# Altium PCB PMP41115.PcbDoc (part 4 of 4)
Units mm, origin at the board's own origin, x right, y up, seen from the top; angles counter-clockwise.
Board outline 97.92 x 43.13 mm, 4 copper layers (Top Layer, Signal Layer 1, Signal Layer 2, Bottom Layer), stack 1.016 mm thick; 168 components, 122 nets, 522 pads, 2459 vias.
Unrouted connection lines stored in the file: 1.
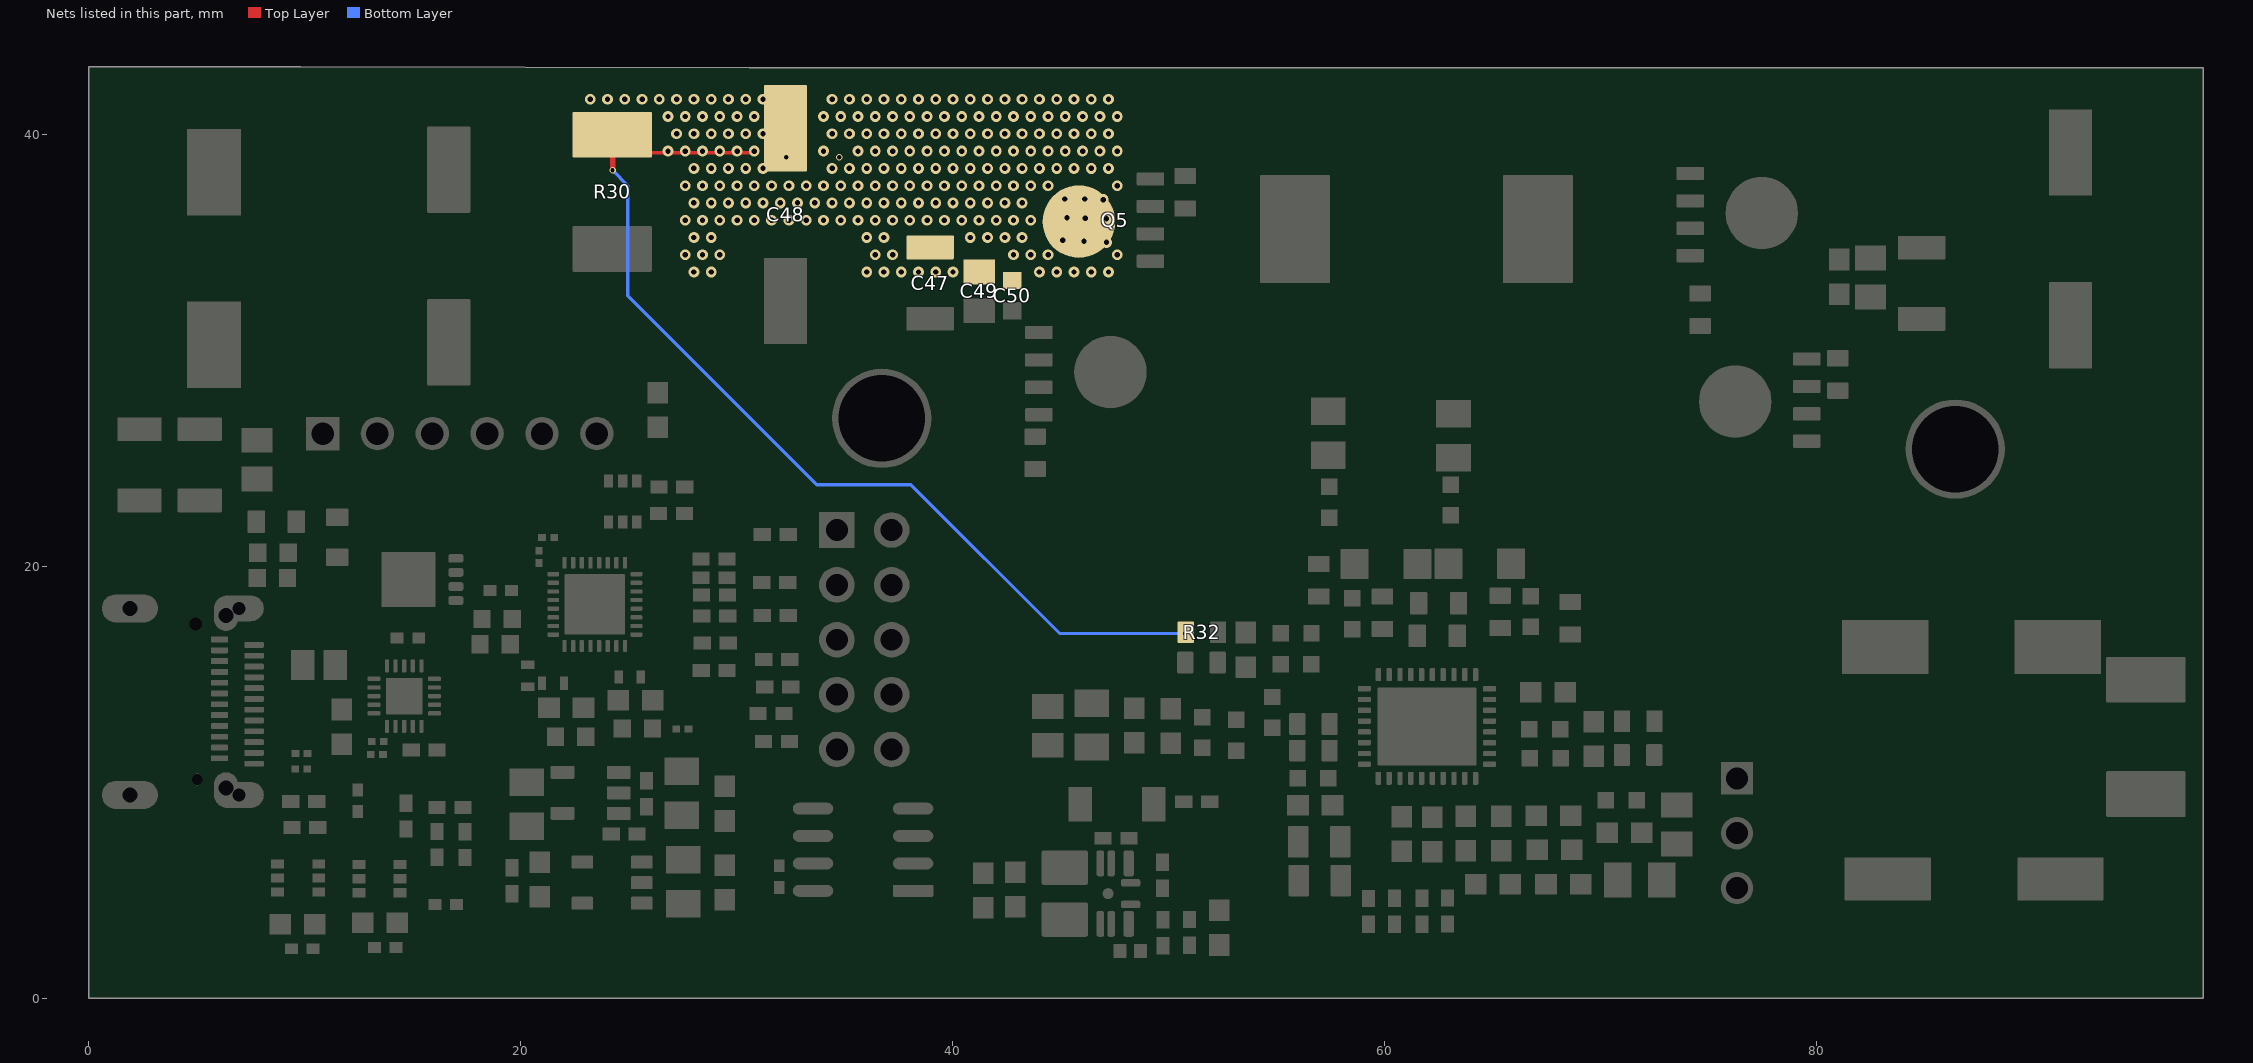
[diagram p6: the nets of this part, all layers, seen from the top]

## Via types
v1: diameter 0.5, hole 0.25, Top Layer to Bottom Layer, 2147 vias
v2: diameter 0.3, hole 0.2, Top Layer to Bottom Layer, tented both sides, 193 vias
v3: diameter 0.5, hole 0.25, Top Layer to Bottom Layer, tented both sides, 61 vias
v4: diameter 0.5, hole 0.2, Top Layer to Bottom Layer, 22 vias
v5: diameter 0.5, hole 0.2, Top Layer to Bottom Layer, tented both sides, 19 vias
v6: diameter 0.61, hole 0.203, Top Layer to Bottom Layer, tented both sides, 13 vias
v7: diameter 0.35, hole 0.2, Top Layer to Bottom Layer, tented both sides, 2 vias
v8: diameter 0.4, hole 0.2, Top Layer to Bottom Layer, tented both sides, 2 vias

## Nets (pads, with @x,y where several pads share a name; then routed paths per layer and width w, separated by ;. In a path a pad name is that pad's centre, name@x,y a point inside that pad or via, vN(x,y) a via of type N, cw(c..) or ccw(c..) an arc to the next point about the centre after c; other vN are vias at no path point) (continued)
VSYS: C47.2 C48.2 C49.1 C50.1 Q5.5-6-7-8 R30.2 R32.2 | length 47
  Top Layer w0.152: R30.2@24.243,39.979 R30.2@24.332,39.89 ; R30.2@24.257,39.091 24.257,39.815 R30.2@24.332,39.89 ; v1@30.863,39.181 30.823,39.141 25.081,39.141 R30.2@24.332,39.89
  Top Layer w0.254: v2(24.257,38.329) 24.257,39.051 24.297,39.091 R30.2@24.308,39.091
  Bottom Layer w0.152: 28.55,28.931 33.706,23.774 38.075,23.774 44.966,16.883 v2(50.764,16.883)
  Bottom Layer w0.154: v2(24.257,38.329) 24.968,37.617 24.968,32.512 28.55,28.931
  other v1: 28.023,33.621 28.823,33.621 36.023,33.621 36.823,33.621 37.623,33.621 38.423,33.621 39.223,33.621 40.023,33.621 44.023,33.621 44.823,33.621 45.623,33.621 46.423,33.621 47.223,33.621 27.623,34.421 28.423,34.421 29.223,34.421 36.423,34.421 37.223,34.421 42.823,34.421 43.623,34.421 44.423,34.421 47.623,34.421 28.023,35.221 28.823,35.221 36.023,35.221 36.823,35.221 40.823,35.221 41.623,35.221 42.423,35.221 43.223,35.221 27.623,36.021 28.423,36.021 29.223,36.021 30.023,36.021 30.823,36.021 31.623,36.021 32.423,36.021 33.223,36.021 34.023,36.021 34.823,36.021 35.623,36.021 36.423,36.021 37.223,36.021 38.023,36.021 38.823,36.021 39.623,36.021 40.423,36.021 41.223,36.021 42.023,36.021 42.823,36.021 43.623,36.021 28.023,36.821 28.823,36.821 29.623,36.821 30.423,36.821 31.223,36.821 32.023,36.821 32.823,36.821 33.623,36.821 34.423,36.821 35.223,36.821 36.023,36.821 36.823,36.821 37.623,36.821 38.423,36.821 39.223,36.821 40.023,36.821 40.823,36.821 41.623,36.821 42.423,36.821 43.223,36.821 27.623,37.621 28.423,37.621 29.223,37.621 30.023,37.621 30.823,37.621 31.623,37.621 32.423,37.621 33.223,37.621 34.023,37.621 34.823,37.621 35.623,37.621 36.423,37.621 37.223,37.621 38.023,37.621 38.823,37.621 39.623,37.621 40.423,37.621 41.223,37.621 42.023,37.621 42.823,37.621 43.623,37.621 44.423,37.621 47.623,37.621 28.023,38.421 28.823,38.421 29.623,38.421 30.423,38.421 31.223,38.421 34.423,38.421 35.223,38.421 36.023,38.421 36.823,38.421 37.623,38.421 38.423,38.421 39.223,38.421 40.023,38.421 40.823,38.421 41.623,38.421 42.423,38.421 43.223,38.421 44.023,38.421 44.823,38.421 45.623,38.421 46.423,38.421 47.223,38.421 26.823,39.221 27.623,39.221 28.423,39.221 29.223,39.221 30.023,39.221 30.823,39.221 34.023,39.221 35.623,39.221 36.423,39.221 37.223,39.221 38.023,39.221 38.823,39.221 39.623,39.221 40.423,39.221 41.223,39.221 42.023,39.221 42.823,39.221 43.623,39.221 44.423,39.221 45.223,39.221 46.023,39.221 46.823,39.221 47.623,39.221 27.223,40.021 28.023,40.021 28.823,40.021 29.623,40.021 30.423,40.021 31.223,40.021 34.423,40.021 35.223,40.021 36.023,40.021 36.823,40.021 37.623,40.021 38.423,40.021 39.223,40.021 40.023,40.021 40.823,40.021 41.623,40.021 42.423,40.021 43.223,40.021 44.023,40.021 44.823,40.021 45.623,40.021 46.423,40.021 47.223,40.021 26.823,40.821 27.623,40.821 28.423,40.821 29.223,40.821 30.023,40.821 30.823,40.821 34.023,40.821 34.823,40.821 35.623,40.821 36.423,40.821 37.223,40.821 38.023,40.821 38.823,40.821 39.623,40.821 40.423,40.821 41.223,40.821 42.023,40.821 42.823,40.821 43.623,40.821 44.423,40.821 45.223,40.821 46.023,40.821 46.823,40.821 47.623,40.821 23.223,41.621 24.023,41.621 24.823,41.621 25.623,41.621 26.423,41.621 27.223,41.621 28.023,41.621 28.823,41.621 29.623,41.621 30.423,41.621 31.223,41.621 34.423,41.621 35.223,41.621 36.023,41.621 36.823,41.621 37.623,41.621 38.423,41.621 39.223,41.621 40.023,41.621 40.823,41.621 41.623,41.621 42.423,41.621 43.223,41.621 44.023,41.621 44.823,41.621 45.623,41.621 46.423,41.621 47.223,41.621
  other v2: 34.747,38.938
  other v3: 47.13,34.995 46.088,35.046 45.098,35.096 47.13,36.087 46.139,36.112 45.301,36.138 46.977,36.976 45.199,37.001 46.114,37.001
  other v6: 32.309,38.938
pads on no net: J1.A2 J1.A3 J1.A10 J1.A11 J1.ALIGN1 J1.ALIGN2 J1.B2 J1.B3 J1.B10 J1.B11 J3.4 Q1.9A Q1.9B Q1.9C Q1.9D U1.21 U2.9 U4.4 U5.1 U5.7 U6.4 U7.15 U7.16 U7.31

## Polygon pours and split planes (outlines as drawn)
VSYS on Top Layer "TOP_LAYER_VSYS_P022" (solid, remove dead copper, pour order 22): 22.198,42.596 22.201,38.684 27.092,38.684 27.044,32.722 29.769,32.722 29.769,35.238 35.364,35.238 35.35,32.723 47.955,32.766 47.955,42.596
NetU5_5 on Top Layer "TOP_LAYER_NETU5_5_P001" (solid, pour order 1): 46.025,2.896 46.05,2.87 47.015,2.87 47.015,3.962 46.965,4.013 46.025,4.013
NetC21_1 on Top Layer "TOP_LAYER_NETC21_1_P115" (solid, remove dead copper, pour order 115): 46.482,7.696 46.482,5.791 46.66,5.613 47.422,5.613 47.523,5.715 47.523,6.807 47.371,6.96 47.371,7.696 46.507,7.696
PPHV on Top Layer "TOP_LAYER_PPHV_P033" (solid, remove dead copper, pour order 33): 0.483,33.223 0.483,24.841 12.065,24.841 12.065,27.127 3.937,27.127 3.937,33.223
VBUS on Top Layer "TOP_LAYER_VBUS_P034" (solid, remove dead copper, pour order 34): 22.174,25.73 18.771,22.327 13.335,22.327 13.335,21.234 10.82,21.234 10.82,16.205 10.82,14.63 13.894,14.63 13.894,17.729 16.408,17.729 16.408,20.142 16.408,20.752 27.457,20.752 27.457,27.127 22.174,27.127
PP5V on Top Layer "TOP_LAYER_PP5V_P114" (solid, remove dead copper, pour order 114): 20.396,18.136 20.828,18.567 21.768,18.567 21.844,18.491 21.844,17.983 21.768,17.907 20.904,17.907 20.371,17.374 20.371,15.85 19.101,15.85 19.101,17.983 19.253,18.136
GND on Top Layer "TOP_LAYER_GND_P095" (solid, remove dead copper, pour order 95): 10.922,11.633 8.23,11.633 8.23,0.61 17.958,0.61 17.958,15.646 10.947,15.646 10.922,15.621
GND on Top Layer "TOP_LAYER_GND_P075" (solid, remove dead copper, pour order 75): 39.821,0.61 79.099,0.61 79.099,6.564 77.552,6.598 77.521,18.948 39.821,18.948
VBUS_LV on Top Layer "TOP_LAYER_VBUS_LV_P054" (solid, remove dead copper, pour order 54): 16.586,17.653 13.919,17.653 13.919,15.646 14.808,15.646 14.808,17.043 17.625,17.043 17.805,17.223 17.805,19.228 18.999,19.228 18.999,18.491 21.692,18.491 21.895,18.694 21.895,19.228 21.742,19.38 21.133,19.38 20.396,20.117 16.586,20.117
GND on Top Layer "TOP_LAYER_GND_P044" (solid, remove dead copper, pour order 44): 17.882,0 41.681,0 41.681,5.436 39.319,5.436 39.319,18.796 17.882,18.796
GND on Top Layer "TOP_LAYER_GND_P036" (solid, remove dead copper, pour order 36): 0.61,4.623 0.61,0.61 8.331,0.61 8.331,24.308 0.61,24.308
GND on Top Layer "TOP_LAYER_GND_P039" (solid, remove dead copper, pour order 39): 12.497,27.813 12.497,24.536 0.686,24.536 0.686,21.641 13.03,21.641 13.03,22.657 19.101,22.657 21.92,25.476 21.92,27.813
VBUS_C on Top Layer "TOP_LAYER_VBUS_C_P038" (solid, remove dead copper, pour order 38): 8.534,22.606 8.534,15.69 6.579,15.705 6.577,13.588 6.579,11.76 10.617,11.76 10.617,22.606
GND on Top Layer "TOP_LAYER_GND_P032" (solid, remove dead copper, pour order 32): 4.115,27.381 28.118,27.408 28.118,21.107 30.378,21.107 30.378,32.41 4.115,32.41
PPHV on Top Layer "TOP_LAYER_PPHV_P031" (solid, remove dead copper, pour order 31): 0.559,42.647 21.514,42.647 21.514,35.763 26.467,35.763 26.467,32.766 20.498,32.766 0.559,32.766
BAT on Top Layer "TOP_LAYER_BAT_P030" (solid, remove dead copper, pour order 30): 88.392,10.338 88.392,0.61 97.434,0.61 97.434,10.338
P_OUT on Top Layer "TOP_LAYER_P_OUT_P029" (solid, remove dead copper, pour order 29): 93.143,33.604 93.089,18.596 88.179,18.596 88.179,13.882 97.739,13.882 97.739,33.604
GND on Top Layer "TOP_LAYER_GND_P028" (solid, remove dead copper, pour order 28): 78.003,0.61 87.478,0.61 87.478,22.149 78.003,22.149
P_OUT on Top Layer "TOP_LAYER_P_OUT_P027" (solid, remove dead copper, pour order 27): 75.311,42.647 75.311,33.426 97.917,33.426 97.917,42.647
GND on Top Layer "TOP_LAYER_GND_P026" (solid, remove dead copper, pour order 26): 78.537,19.177 85.7,19.177 93.269,19.177 93.269,33.249 78.537,33.249
SW2 on Top Layer "TOP_LAYER_SW2_P025" (solid, remove dead copper, pour order 25): 60.858,23.52 78.207,23.52 78.207,32.461 74.969,32.461 75.006,42.672 60.858,42.672
SW1 on Top Layer "TOP_LAYER_SW1_P024" (solid, remove dead copper, pour order 24): 48.235,42.596 48.235,32.741 48.006,32.512 45.187,32.512 45.187,23.647 59.893,23.647 59.893,42.596
GND on Top Layer "TOP_LAYER_GND_P023" (solid, remove dead copper, pour order 23): 29.186,34.773 29.186,19.101 83.439,19.101 83.439,23.216 45.009,23.216 45.009,34.773
BAT on Bottom Layer "BOTTOM_LAYER_BAT_P146" (solid, remove dead copper, pour order 146): 88.392,10.338 88.392,0.61 97.434,0.61 97.434,10.338
P_OUT on Bottom Layer "BOTTOM_LAYER_P_OUT_P145" (solid, remove dead copper, pour order 145): 93.143,33.604 93.089,18.596 88.179,18.596 88.179,13.882 97.739,13.882 97.739,33.604
GND on Bottom Layer "BOTTOM_LAYER_GND_P144" (solid, remove dead copper, pour order 144): 78.003,0.61 87.478,0.61 87.478,22.149 78.003,22.149
P_OUT on Bottom Layer "BOTTOM_LAYER_P_OUT_P143" (solid, remove dead copper, pour order 143): 75.311,42.647 75.311,33.426 97.917,33.426 97.917,42.647
GND on Bottom Layer "BOTTOM_LAYER_GND_P142" (solid, remove dead copper, pour order 142): 78.537,19.177 85.7,19.177 93.269,19.177 93.269,33.249 78.537,33.249
SW2 on Bottom Layer "BOTTOM_LAYER_SW2_P141" (solid, remove dead copper, pour order 141): 60.858,23.52 78.207,23.52 78.207,32.461 74.969,32.461 75.006,42.672 60.858,42.672
VBUS on Bottom Layer "BOTTOM_LAYER_VBUS_P005" (solid, remove dead copper, pour order 5): 22.276,25.654 18.872,22.25 13.437,22.25 13.437,21.158 10.922,21.158 10.922,16.129 10.922,14.554 13.995,14.554 13.995,17.653 16.51,17.653 16.51,20.066 16.51,20.676 27.559,20.676 27.559,27.051 22.276,27.051
PPHV on Bottom Layer "BOTTOM_LAYER_PPHV_P007" (solid, remove dead copper, pour order 7): 0.662,32.944 0.662,24.867 12.065,24.867 12.065,27.153 3.937,27.153 3.937,32.944
GND on Bottom Layer "BOTTOM_LAYER_GND_P050" (solid, remove dead copper, pour order 50): 39.745,10.361 52.934,10.365 52.934,2.972 77.902,2.972 77.902,19.025 39.745,19.025
VSYS on Bottom Layer "BOTTOM_LAYER_VSYS_P004" (solid, remove dead copper, pour order 4): 22.198,42.57 22.201,38.659 27.126,38.659 27.078,32.696 29.769,32.696 29.769,35.212 35.364,35.212 35.35,32.698 47.955,32.741 47.955,42.57
GND on Bottom Layer "BOTTOM_LAYER_GND_P120" (solid, remove dead copper, pour order 120): 35.159,32.398 35.159,35.031 29.931,35.031 29.931,32.371 27.813,32.36 27.813,19.329 80.899,19.329 80.899,23.089 44.602,23.089 44.602,32.36
PPHV on Bottom Layer "BOTTOM_LAYER_PPHV_P051" (solid, remove dead copper, pour order 51): 0.555,42.567 21.51,42.567 21.51,34.922 23.19,34.922 23.19,32.686 20.494,32.686 0.555,32.686
SW1 on Bottom Layer "BOTTOM_LAYER_SW1_P047" (solid, remove dead copper, pour order 47): 48.158,42.596 48.158,32.69 47.93,32.461 45.11,32.461 45.11,23.597 59.766,23.597 59.766,42.596
GND on Bottom Layer "BOTTOM_LAYER_GND_P046" (solid, remove dead copper, pour order 46): 35.179,0 77.902,0 77.902,10.312 35.179,10.312
GND on Bottom Layer "BOTTOM_LAYER_GND_P045" (solid, remove dead copper, pour order 45): 0.559,32.309 0.559,0.533 38.989,0.533 38.989,32.309
BAT on Signal Layer 1 "SIGNAL_LAYER_1_BAT_P134" (solid, remove dead copper, pour order 134): 88.392,10.338 88.392,0.61 97.434,0.61 97.434,10.338
P_OUT on Signal Layer 1 "SIGNAL_LAYER_1_P_OUT_P133" (solid, remove dead copper, pour order 133): 93.143,33.604 93.089,18.596 88.179,18.596 88.179,13.882 97.739,13.882 97.739,33.604
GND on Signal Layer 1 "SIGNAL_LAYER_1_GND_P132" (solid, remove dead copper, pour order 132): 78.003,0.61 87.478,0.61 87.478,22.149 78.003,22.149
P_OUT on Signal Layer 1 "SIGNAL_LAYER_1_P_OUT_P131" (solid, remove dead copper, pour order 131): 75.311,42.647 75.311,33.426 97.917,33.426 97.917,42.647
GND on Signal Layer 1 "SIGNAL_LAYER_1_GND_P130" (solid, remove dead copper, pour order 130): 78.537,19.177 85.7,19.177 92.837,19.177 92.837,33.249 78.537,33.249
SW2 on Signal Layer 1 "SIGNAL_LAYER_1_SW2_P129" (solid, remove dead copper, pour order 129): 60.858,23.52 78.207,23.52 78.207,32.487 74.969,32.487 75.006,42.672 60.858,42.672
GND on Signal Layer 1 "SIGNAL_LAYER_1_GND_P057" (solid, remove dead copper, pour order 57): 28.702,35.433 28.702,19.253 81.356,19.253 81.356,23.216 45.06,23.216 45.06,35.433
VSYS on Signal Layer 1 "SIGNAL_LAYER_1_VSYS_P118" (solid, remove dead copper, pour order 118): 22.198,42.57 22.201,38.659 27.092,38.659 27.044,32.696 29.769,32.696 29.769,35.212 35.364,35.212 35.35,32.698 47.955,32.741 47.955,42.57
VBUS on Signal Layer 1 "SIGNAL_LAYER_1_VBUS_P112" (solid, remove dead copper, pour order 112): 22.123,25.679 18.72,22.276 13.284,22.276 13.284,21.184 10.77,21.184 10.77,16.154 10.77,15.875 13.843,15.875 13.843,17.678 16.358,17.678 16.358,20.091 16.358,20.701 26.924,20.701 26.924,27.076 22.123,27.076
PPHV on Signal Layer 1 "SIGNAL_LAYER_1_PPHV_P111" (solid, remove dead copper, pour order 111): 0.611,32.868 0.611,24.79 12.014,24.79 12.014,27.076 3.886,27.076 3.886,32.868
GND on Signal Layer 1 "SIGNAL_LAYER_1_GND_P073" (solid, remove dead copper, pour order 73): 10.973,11.633 8.28,11.633 8.28,0.33 18.009,0.33 18.009,15.646 10.998,15.646 10.973,15.621
GND on Signal Layer 1 "SIGNAL_LAYER_1_GND_P072" (solid, remove dead copper, pour order 72): 39.623,4.623 78.054,4.623 78.054,18.948 39.623,18.948
GND on Signal Layer 1 "SIGNAL_LAYER_1_GND_P071" (solid, remove dead copper, pour order 71): 16.205,0.66 78.029,0.66 78.029,5.436 41.732,5.436 39.37,5.436 39.37,19.888 16.205,19.888
GND on Signal Layer 1 "SIGNAL_LAYER_1_GND_P070" (solid, remove dead copper, pour order 70): 12.548,27.813 12.548,24.536 0.737,24.536 0.737,21.641 12.878,21.641 12.878,22.428 18.923,22.428 21.971,25.476 21.971,27.813
VBUS_C on Signal Layer 1 "SIGNAL_LAYER_1_VBUS_C_P056" (solid, remove dead copper, pour order 56): 8.585,21.565 8.585,15.69 6.629,15.705 6.628,13.588 6.63,11.76 10.668,11.76 10.668,21.565
GND on Signal Layer 1 "SIGNAL_LAYER_1_GND_P069" (solid, remove dead copper, pour order 69): 0.66,4.623 0.66,0.432 8.407,0.432 8.407,4.623 8.407,24.308 0.66,24.308
GND on Signal Layer 1 "SIGNAL_LAYER_1_GND_P066" (solid, remove dead copper, pour order 66): 4.166,27.381 28.169,27.408 28.169,21.107 30.429,21.107 30.429,32.41 4.166,32.41
PPHV on Signal Layer 1 "SIGNAL_LAYER_1_PPHV_P065" (solid, remove dead copper, pour order 65): 0.61,42.647 21.565,42.647 21.565,35.763 26.518,35.763 26.518,32.766 20.549,32.766 0.61,32.766
SW1 on Signal Layer 1 "SIGNAL_LAYER_1_SW1_P058" (solid, remove dead copper, pour order 58): 48.285,42.647 48.285,32.741 48.057,32.512 45.237,32.512 45.237,23.647 59.893,23.647 59.893,42.647
BAT on Signal Layer 2 "SIGNAL_LAYER_2_BAT_P140" (solid, remove dead copper, pour order 140): 88.392,10.338 88.392,0.61 97.434,0.61 97.434,10.338
P_OUT on Signal Layer 2 "SIGNAL_LAYER_2_P_OUT_P139" (solid, remove dead copper, pour order 139): 93.143,33.604 93.089,18.596 88.179,18.596 88.179,13.882 97.739,13.882 97.739,33.604
GND on Signal Layer 2 "SIGNAL_LAYER_2_GND_P138" (solid, remove dead copper, pour order 138): 78.003,0.61 87.478,0.61 87.478,22.149 78.003,22.149
P_OUT on Signal Layer 2 "SIGNAL_LAYER_2_P_OUT_P137" (solid, remove dead copper, pour order 137): 75.311,42.647 75.311,33.426 97.917,33.426 97.917,42.647
GND on Signal Layer 2 "SIGNAL_LAYER_2_GND_P136" (solid, remove dead copper, pour order 136): 78.537,19.177 85.7,19.177 93.269,19.177 93.269,33.249 78.537,33.249
SW2 on Signal Layer 2 "SIGNAL_LAYER_2_SW2_P135" (solid, remove dead copper, pour order 135): 60.858,23.52 78.207,23.52 78.207,32.461 74.969,32.461 75.006,42.672 60.858,42.672
VSYS on Signal Layer 2 "SIGNAL_LAYER_2_VSYS_P119" (solid, remove dead copper, pour order 119): 22.198,42.57 22.201,38.659 27.092,38.659 27.044,32.696 29.769,32.696 29.769,35.212 35.364,35.212 35.35,32.698 47.955,32.741 47.955,42.57
GND on Signal Layer 2 "SIGNAL_LAYER_2_GND_P094" (solid, remove dead copper, pour order 94): 10.998,15.596 8.306,15.596 8.306,0.686 18.034,0.686 18.034,15.621 11.024,15.621
GND on Signal Layer 2 "SIGNAL_LAYER_2_GND_P093" (solid, remove dead copper, pour order 93): 39.929,4.597 78.08,4.597 78.08,18.923 39.929,18.923
GND on Signal Layer 2 "SIGNAL_LAYER_2_GND_P092" (solid, remove dead copper, pour order 92): 16.332,0.66 78.003,0.66 78.003,5.41 41.758,5.41 39.395,5.41 39.395,19.71 16.332,19.71
GND on Signal Layer 2 "SIGNAL_LAYER_2_GND_P091" (solid, remove dead copper, pour order 91): 12.573,27.788 12.573,24.511 0.66,24.511 0.66,21.615 12.319,21.615 12.319,23.622 20.168,23.622 21.996,25.451 21.996,27.788
VBUS_C on Signal Layer 2 "SIGNAL_LAYER_2_VBUS_C_P090" (solid, remove dead copper, pour order 90): 8.611,22.581 8.611,15.665 8.611,15.342 10.693,15.342 10.693,22.581
GND on Signal Layer 2 "SIGNAL_LAYER_2_GND_P089" (solid, remove dead copper, pour order 89): 0.686,4.597 0.686,0.635 8.433,0.635 8.433,4.597 8.433,24.282 0.686,24.282
VBUS on Signal Layer 2 "SIGNAL_LAYER_2_VBUS_P088" (solid, remove dead copper, pour order 88): 22.25,25.705 19.964,23.419 12.675,23.419 12.675,21.209 10.897,21.209 10.897,16.18 10.897,14.605 13.97,14.605 13.97,17.704 16.485,17.704 16.485,20.117 16.485,20.726 27.051,20.726 27.051,27.102 22.25,27.102
PPHV on Signal Layer 2 "SIGNAL_LAYER_2_PPHV_P087" (solid, remove dead copper, pour order 87): 0.279,32.893 0.279,24.816 12.141,24.816 12.141,27.102 4.013,27.102 4.013,32.893
GND on Signal Layer 2 "SIGNAL_LAYER_2_GND_P086" (solid, remove dead copper, pour order 86): 4.191,27.356 28.194,27.383 28.194,21.082 30.455,21.082 30.455,32.385 4.191,32.385
PPHV on Signal Layer 2 "SIGNAL_LAYER_2_PPHV_P085" (solid, remove dead copper, pour order 85): 0.635,42.621 21.59,42.621 21.59,35.738 26.543,35.738 26.543,32.741 20.574,32.741 0.635,32.741
SW1 on Signal Layer 2 "SIGNAL_LAYER_2_SW1_P078" (solid, remove dead copper, pour order 78): 48.311,42.621 48.311,32.715 48.082,32.487 45.263,32.487 45.263,23.622 59.919,23.622 59.919,42.621
GND on Signal Layer 2 "SIGNAL_LAYER_2_GND_P077" (solid, remove dead copper, pour order 77): 28.219,35.941 28.219,19.431 80.289,19.431 80.289,23.19 45.085,23.19 45.085,35.941

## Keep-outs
Keep-Out Layer:
  text ".Layer_Name" at 14.656,-21.222 h1.52

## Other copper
Top Layer:
  text ".Layer_Name" at 14.656,-21.222 h1.52
Bottom Layer:
  text ".Layer_Name" at 14.656,-21.222 h1.52

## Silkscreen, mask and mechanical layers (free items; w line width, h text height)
Top Overlay:
  text "High Temp !" at 45.618,24.098 h2
  text "High Temp !" at 67.437,23.92 h2
  text ".Layer_Name" at 14.656,-21.222 h1.52
Bottom Overlay:
  text ".Layer_Name" at 14.656,-21.222 h1.52
Top Paste:
  text ".Layer_Name" at 14.656,-21.222 h1.52
Bottom Paste:
  text ".Layer_Name" at 14.656,-21.222 h1.52
Top Solder:
  rectangle: 1.27,34.366 20.726,41.859
  rectangle: 88.621,14.351 96.952,18.059
  rectangle: 88.951,1.219 97.079,8.661
  rectangle: 78.689,1.219 86.97,20.93
  rectangle: 93.904,15.773 97.079,34.646
  rectangle: 76.073,34.011 97.13,42.113
  rectangle: 48.717,31.623 52.095,35.433
  rectangle: 35.712,33.223 47.727,36.22
  rectangle: 29.134,36.017 47.752,42.316
  rectangle: 64.973,24.028 78.029,30.226
  rectangle: 45.593,24.054 55.753,31.826
  rectangle: 61.214,26.34 72.923,42.113
  rectangle: 51.816,26.441 59.36,42.189
  rectangle: 82.575,19.888 92.38,29.82
  rectangle: 31.75,23.216 41.783,30.15
  text ".Layer_Name" at 14.656,-21.222 h1.52
  text ".Layer_Name" at 14.656,-21.222 h1.52
Bottom Solder:
  rectangle: 88.632,14.275 96.749,18.159
  rectangle: 1.092,25.349 3.404,33.985
  rectangle: 5.08,28.067 23.495,31.826
  rectangle: 59.385,10.566 64.745,14.656
  rectangle: 45.644,19.71 82.169,22.581
  rectangle: 1.041,33.706 20.574,41.834
  rectangle: 79.019,14.249 86.716,22.631
  rectangle: 94.132,18.059 96.723,34.671
  rectangle: 82.144,19.609 92.227,32.537
  region: 33.844,24.464 42.45,24.48 42.437,31.481 33.831,31.465
  rectangle: 27.711,35.712 47.777,41.885
  rectangle: 75.794,34.493 96.723,42.088
  rectangle: 45.872,23.978 49.682,31.826
  rectangle: 48.514,37.871 53.137,41.91
  rectangle: 66.37,32.817 74.651,42.037
  rectangle: 66.853,24.028 77.622,29.997
  rectangle: 61.392,24.079 70.841,42.037
  rectangle: 52.553,33.858 58.953,41.885
  rectangle: 48.768,24.003 58.928,35.204
  rectangle: 88.722,2.633 96.85,8.5
  rectangle: 79.121,2.692 87.249,8.509
  text ".Layer_Name" at 14.656,-21.222 h1.52
Drill Guide:
  text ".Layer_Name" at 14.656,-21.222 h1.52
M1 Board Outline:
  lines w0.2: 0,43.129 9.804,43.129 ; 9.83,43.129 30.582,43.078 ; 30.556,43.078 53.188,43.078 ; 53.238,43.078 97.917,43.078 97.917,0
  lines w0.254: 0,43.129 0,0 97.917,0
  text ".Layer_Name" at 14.656,-21.222 h1.52
M2 Board Dimensions:
  rectangle: 0,-6.401 3.175,-3.226
  rectangle: 3.175,-9.576 12.7,-6.401
  lines w0.178: 0,-6.401 25.4,-6.401 ; 3.175,-9.576 3.175,-3.226 ; 6.35,-9.576 6.35,-3.226 ; 12.7,-9.576 12.7,-3.226 ; 19.05,-9.576 19.05,-3.226 ; 0,-9.576 25.4,-9.576 25.4,-3.226 0,-3.226 0,-9.576
  text ".Layer_Name" at 14.656,-21.222 h1.52
M3 3D STEP Top:
  text ".Layer_Name" at 14.656,-21.222 h1.52
M4 3D STEP Bottom:
  text ".Layer_Name" at 14.656,-21.222 h1.52
M5 Assembly Top:
  lines w0.254: -7.417,-23.042 160.223,-23.042 ; -7.417,-17.877 160.274,-17.877 ; -7.417,-12.713 -7.417,-28.207 94.31,-28.207 160.274,-28.207 160.274,-12.713 -7.404,-12.713 -7.404,-28.207 32.614,-28.207 ; 55.194,-28.207 55.194,-12.713 ; 87.376,-17.877 87.376,-12.713 ; 108.712,-17.877 108.712,-12.713 ; 124.511,-28.372 124.511,-23.22
  text "COMPONENTS MARKED 'DNP' SHOULD NOT BE POPULATED." at 29.299,-7.506 h1.52
  text "ASSEMBLY VARIANT:" at 29.286,-10.439 h1.52
  text ".VariantName" at 55.601,-10.439 h1.52
  text "PCB VIEWED FROM TOP SIDE" at -5.804,-16.07 h1.52
  text "BOARD #:" at 57.099,-16.07 h1.52
  text ".PRJ_Number" at 70.955,-16.07 h1.52
  text "REV:" at 92.405,-16.07 h1.52
  text ".PCB_Rev" at 99.809,-16.07 h1.52
  text "SVN REV:" at 113.69,-16.07 h1.52
  text ".VersionControl_RevNumber" at 126.543,-16.07 h1.52
  text "TID #:" at 57.099,-21.234 h1.52
  text ".TID" at 70.955,-21.234 h1.52
  text "PLOT NAME =" at -5.804,-26.45 h1.52
  text ".plot_File_Name" at 14.656,-26.45 h1.52
  text "GENERATED    :" at 57.15,-26.45 h1.52
  text ".Print_Date" at 79.235,-26.45 h1.52
  text ".Print_Time" at 97.752,-26.45 h1.52
  text "TEXAS INSTRUMENTS" at 129.87,-26.45 h1.52
M6 Assembly Bottom:
  lines w0.254: -7.429,-17.89 160.261,-17.89 ; -7.379,-23.055 160.261,-23.055 ; 28.334,-28.384 28.334,-23.233 ; 44.133,-17.89 44.133,-12.725 ; 65.468,-17.89 65.468,-12.725 ; 97.65,-28.219 97.65,-12.725 ; 120.231,-28.219 160.249,-28.219 160.249,-12.725 -7.429,-12.725 -7.429,-28.219 58.534,-28.219 160.261,-28.219 160.261,-12.725
  text "COMPONENTS MARKED 'DNP' SHOULD NOT BE POPULATED." at 154.991,-7.493 h1.52
  text ".VariantName" at 128.473,-10.439 h1.52
  text "ASSEMBLY VARIANT:" at 154.864,-10.439 h1.52
  text ".VersionControl_RevNumber" at 26.302,-16.082 h1.52
  text "SVN REV:" at 39.154,-16.082 h1.52
  text ".PCB_Rev" at 53.035,-16.082 h1.52
  text "REV:" at 60.439,-16.082 h1.52
  text ".PRJ_Number" at 81.89,-16.082 h1.52
  text "BOARD #:" at 95.745,-16.082 h1.52
  text "PCB VIEWED FROM BOTTOM SIDE" at 158.648,-16.082 h1.52
  text ".TID" at 81.89,-21.247 h1.52
  text "TID #:" at 95.745,-21.247 h1.52
  text "TEXAS INSTRUMENTS" at 22.974,-26.463 h1.52
  text ".Print_Time" at 55.093,-26.463 h1.52
  text ".Print_Date" at 73.609,-26.463 h1.52
  text "GENERATED    :" at 95.694,-26.463 h1.52
  text ".plot_File_Name" at 138.189,-26.463 h1.52
  text "PLOT NAME =" at 158.648,-26.463 h1.52
M9 Title Sheet:
  drawing of 57 lines, arcs and shapes, not listed
  text "1" at 18.792,204.711 h1.78
  text "2" at 82.182,204.711 h1.78
  text "3" at 145.411,204.711 h1.78
  text "4" at 209.08,204.711 h1.78
  text "5" at 272.555,204.711 h1.78
  text "6" at 336.182,204.711 h1.78
  text "A" at -10.579,175.679 h1.78
  text "A" at 365.341,175.679 h1.78
  text "B" at -10.579,115.227 h1.78
  text "B" at 365.341,115.227 h1.78
  text "C" at -10.579,54.902 h1.78
  text "C" at 365.341,54.902 h1.78
  text "PROJECT TITLE:" at 288.125,7.633 h1.14
  text ".PRJ_Title" at 289.395,4.246 h1.78
  text "DESIGNED FOR:" at 288.125,-0.013 h1.14
  text ".PRJ_Customer" at 289.395,-3.569 h1.78
  text "D" at -10.579,-5.296 h1.78
  text "D" at 365.341,-5.296 h1.78
  text "FILE NAME:" at 288.125,-7.633 h1.14
  text ".PCB_File_Name_No_Path" at 289.395,-10.681 h1.78
  text "Texas Instruments (TI) and/or its licensors do not warrant the accuracy or completeness of this specification" at 161.9,-14.791 h1.14
  text "ENGINEER:" at 288.125,-14.999 h1.14
  text "LAYOUT BY:" at 326.352,-14.999 h1.14
  text "or any information contained therein. TI and/or its licensors do not warrant that this design will meet" at 160.757,-17.653 h1.14
  text ".PRJ_Engineer" at 289.395,-18.936 h1.78
  text ".PCB_Layout" at 327.635,-18.936 h1.78
  text "the specifications, will be suitable for your application or fit for any particular purpose, or will operate in" at 160.757,-20.515 h1.14
  text ".Layer_Name" at 14.656,-21.222 h1.52
  text "ALTIUM DESIGNER VERSION:" at 326.352,-22.873 h1.14
  text "an implementation. TI and/or its licensors do not warrant that the design is production worthy. You should" at 160.757,-23.376 h1.14
  text "completely validate and test your design implementation to confirm the system functionality for your application." at 161.9,-26.238 h1.14
  text ".print_Scale" at 289.395,-26.259 h1.78
  text ".Application_BuildNumber" at 327.635,-26.259 h1.78
  text "1" at 18.792,-31.509 h1.78
  text "2" at 82.182,-31.509 h1.78
  text "3" at 145.411,-31.509 h1.78
  text "4" at 209.08,-31.509 h1.78
  text "5" at 272.555,-31.509 h1.78
  text "6" at 336.182,-31.509 h1.78
M10 Fab Notes:
  drawing of 189 lines, arcs and shapes, not listed
  text "DESIGN INFORMATION" at 314.503,162.031 h1.52
  text "MIN. TRACK WIDTH:" at 298.131,158.675 h1.52
  text "8" at 325.976,158.675 h1.52
  text "MIL" at 329.907,158.675 h1.52
  text "7.874" at 321.75,155.584 h1.52
  text "MIN. CLEARANCE:" at 298.131,155.522 h1.52
  text "MIL" at 329.907,155.522 h1.52
  text "MIN. VIA PAD SIZE:" at 298.131,152.369 h1.52
  text "24" at 325.214,152.369 h1.52
  text "MIL" at 329.907,152.369 h1.52
  text "0.05mm (2MIL)" at 315.784,149.07 h1.52
  text "MINIMUM ANNULAR RING" at 289.769,148.861 h1.52
  text "EXTERNAL" at 333.768,148.861 h1.52
  text "PER" at 294.849,146.064 h1.52
  text "IPC-D-275 CLASS 2 LEVEL C" at 300.437,146.064 h1.52
  text "MIL, HOLES" at 338.238,143.512 h1.52
  text "+/-" at 328.27,143.294 h1.52
  text "+/-" at 349.961,143.294 h1.52
  text "REGISTRATION TOLERANCES:" at 289.769,143.267 h1.52
  text "METAL" at 320.243,143.267 h1.52
  text "5" at 334.879,143.267 h1.52
  text "3" at 356.037,143.267 h1.52
  text "MIL" at 358.99,143.267 h1.52
  text "HOLE SIZE TOLERANCE (UNLESS OTHERWISE SPECIFIED):" at 289.769,140.769 h1.52
  text "+/-" at 349.961,140.696 h1.52
  text "3" at 356.037,140.67 h1.52
  text "MIL" at 358.99,140.669 h1.52
  text "MATERIAL:" at 287.87,137.173 h1.52
  text "FR-4 High Tg" at 312.926,133.909 h1.52
  text "X" at 309.257,133.706 h1.52
  text "FR-4" at 298.563,133.591 h1.52
  text "OTHER" at 336.358,133.591 h1.52
  text "62 MIL (1.6mm) +/-10%" at 306.694,129.958 h1.52
  text "X" at 303.643,129.896 h1.52
  text "THICKNESS:" at 289.769,129.749 h1.52
  text "OTHER" at 339.33,129.749 h1.52
  text "TOLERANCE:" at 289.769,126.236 h1.52
  text "X" at 311.314,126.236 h1.52
  text "ANSI IPC-6012 TYPE 3 CLASS 2" at 315.836,126.236 h1.52
  text "OTHER +/-" at 315.835,122.574 h1.52
  text "BOW & TWIST:" at 289.769,118.886 h1.52
  text "X" at 311.314,118.886 h1.52
  text "ANSI IPC-6012 TYPE 3 CLASS 2" at 315.836,118.886 h1.52
  text "OTHER +/-" at 315.835,115.16 h1.52
  text "DRILLING:" at 287.87,111.842 h1.52
  text "NC_DRILL FILES" at 332.599,109.17 h1.52
  text "REFERENCE:" at 289.769,109.07 h1.52
  text "X" at 306.463,109.068 h1.52
  text "AS SHOWN" at 310.984,109.07 h1.52
  text "X" at 329.348,109.07 h1.52
  text "OTHER" at 340.168,105.457 h1.52
  text "PTH COPPER THICKNESS:" at 289.761,105.367 h1.52
  text "X" at 318.697,105.367 h1.52
  text "20-30 um" at 321.948,105.367 h1.52
  text "BOARD FINISH:" at 287.87,101.618 h1.52
  text "SILKSCREEN:" at 291.812,98.821 h1.52
  text "X" at 316.14,98.821 h1.52
  text "TOP" at 319.112,98.821 h1.52
  text "X" at 329.094,98.821 h1.52
  text "BOTTOM" at 332.091,98.821 h1.52
  text "SILKSCREEN COLOR:" at 291.812,94.879 h1.52
  text "X" at 316.115,94.879 h1.52
  text "WHITE" at 319.112,94.879 h1.52
  text "OTHER" at 332.091,94.879 h1.52
  text "X" at 319.442,91.236 h1.52
  text "GREEN" at 322.439,91.236 h1.52
  text "OTHER" at 338.136,91.236 h1.52
  text "SOLDER RESIST COLOR:" at 291.812,91.061 h1.52
  text "X" at 319.442,87.318 h1.52
  text "MATTE" at 322.439,87.318 h1.52
  text "SEMI-GLOSS" at 338.125,87.302 h1.52
  text "IMMERSION GOLD (ENIG)" at 314.819,82.929 h1.52
  text "ENEPIG" at 348.793,82.746 h1.52
  text "SURFACE FINISH:" at 287.87,82.721 h1.52
  text "X" at 310.298,82.721 h1.52
  text "IMM. TIN/SILVER OR EQUIV" at 296.24,79.233 h1.52
  text "OTHER" at 332.599,79.133 h1.52
  text "ARRAY/PANEL:" at 287.87,75.186 h1.52
  text "CUT AND TRIM PER M1 BOARD OUTLINE" at 314.819,74.977 h1.52
  text "N.C. ROUTE" at 314.819,71.524 h1.52
  text "X" at 332.295,71.524 h1.52
  text "V. SCORE" at 336.816,71.524 h1.52
  text "CERTIFICATION:" at 287.87,68.244 h1.52
  text "MATERIALS AND WORKMANSHIP FOR ALL PCBS" at 306.285,68.244 h1.52
  text "TO MEET OR EXCEED THE REQUIREMENTS OF:" at 306.285,65.855 h1.52
  text "X" at 297.078,62.588 h1.52
  text "ANSI IPC-A-600F CLASS ->" at 300.329,62.588 h1.52
  text "X" at 342.188,62.588 h1.52
  text "2" at 344.982,62.588 h1.52
  text "1" at 336.981,62.55 h1.52
  text "3" at 353.973,62.55 h1.52
  text "X" at 317.702,58.836 h1.52
  text "RoHS" at 320.953,58.836 h1.52
  text "OTHER" at 337.321,58.836 h1.52
  text "PER ORDER" at 347.407,58.836 h1.52
  text "ALL BOARDS MUST MEET OR EXCEED UL94-V0 REQUIREMENTS." at 288.569,54.929 h1.52
  text "PCB MUST BEAR THE UL94V-0 UL REGISTERED MATERIAL ID NUMBER" at 288.569,51.981 h1.52
  text "ADDITIONAL REQUIREMENTS:" at 287.87,47.678 h1.52
  text "MICROSECTION:" at 289.769,44.957 h1.52
  text "YES" at 312.775,44.957 h1.52
  text "REQUIRED" at 334.657,41.291 h1.52
  text "BARE BOARD ELEC. TEST:" at 289.769,41.218 h1.52
  text "NONE" at 322.935,41.218 h1.52
  text "X" at 331.66,41.218 h1.52
  text "PER ORDER" at 349.693,41.218 h1.52
  text "XX MIL VIAS REQUIRE NON-CONDUCTIVE FILL AND PLANARIZE" at 294.04,36.013 h1.5
  text "XX MIL VIAS REQUIRE CONDUCTIVE FILL AND PLANARIZE" at 294.243,33.372 h1.52
  text "OUTER XX MIL TRACES REQUIRE 50 OHM SINGLE-ENDED IMPEDANCE" at 294.218,29.222 h1.47
  text "LAYER 2 & 3 (INNER LAYERS) XX MIL WIDE, XX MIL SPACE / TRACES REQUIRE 100 OHM DIFFERENTIAL IMPEDANCE" at 294.015,23.235 h1.52
  text ".Layer_Name" at 14.656,-21.222 h1.52
M11 Gerber Information:
  lines w0.254: -7.417,-23.042 160.223,-23.042 ; -7.417,-17.877 160.274,-17.877 ; -7.417,-12.713 -7.417,-28.207 94.31,-28.207 160.274,-28.207 160.274,-12.713 -7.404,-12.713 -7.404,-28.207 32.614,-28.207 ; 55.194,-28.207 55.194,-12.713 ; 87.376,-17.877 87.376,-12.713 ; 108.712,-17.877 108.712,-12.713 ; 124.511,-28.372 124.511,-23.22
  text "ALL ARTWORK VIEWED FROM TOP SIDE" at -5.804,-16.07 h1.52
  text "BOARD #:" at 57.099,-16.07 h1.52
  text ".PRJ_Number" at 70.955,-16.07 h1.52
  text "REV:" at 92.405,-16.07 h1.52
  text ".PCB_Rev" at 99.809,-16.07 h1.52
  text "SVN REV:" at 113.69,-16.07 h1.52
  text ".VersionControl_RevNumber" at 126.543,-16.07 h1.52
  text "LAYER NAME =" at -5.804,-21.222 h1.52
  text "TID #:" at 57.099,-21.234 h1.52
  text ".TID" at 70.955,-21.234 h1.52
  text "PLOT NAME =" at -5.804,-26.45 h1.52
  text ".plot_File_Name" at 14.656,-26.45 h1.52
  text "GENERATED    :" at 57.15,-26.45 h1.52
  text ".Print_Date" at 79.235,-26.45 h1.52
  text ".Print_Time" at 97.752,-26.45 h1.52
  text "TEXAS INSTRUMENTS" at 129.87,-26.45 h1.52
M12 Stackup:
  drawing of 295 lines, arcs and shapes, not listed
  text "Layer" at 249.469,200.608 h1.52
  text "Name" at 259.88,200.608 h1.52
  text "Material" at 283.75,200.608 h1.52
  text "Thickness" at 305.588,200.608 h1.52
  text "Constant" at 322.094,200.608 h1.52
  text "Board Layer Stack" at 336.568,200.608 h1.52
  text "Top Overlay" at 259.88,197.56 h1.52
  text "Top Solder" at 259.88,194.512 h1.52
  text "Solder Resist" at 283.75,194.512 h1.52
  text "0.40mil" at 305.588,194.512 h1.52
  text "3.5" at 322.094,194.512 h1.52
  text "1" at 249.469,191.464 h1.52
  text "Top Layer" at 259.88,191.464 h1.52
  text "1.40mil" at 305.588,191.464 h1.52
  text "Dielectric 1" at 259.88,188.416 h1.52
  text "FR-4 High Tg" at 283.75,188.416 h1.52
  text "5.00mil" at 305.588,188.416 h1.52
  text "4.2" at 322.094,188.416 h1.52
  text "2" at 249.469,185.368 h1.52
  text "Signal Layer 1" at 259.88,185.368 h1.52
  text "1.40mil" at 305.588,185.368 h1.52
  text "Dielectric 2" at 259.88,182.32 h1.52
  text "FR-4 High Tg" at 283.75,182.32 h1.52
  text "24.40mil" at 305.588,182.32 h1.52
  text "4.2" at 322.094,182.32 h1.52
  text "3" at 249.469,179.272 h1.52
  text "Signal Layer 2" at 259.88,179.272 h1.52
  text "1.40mil" at 305.588,179.272 h1.52
  text "Dielectric 3" at 259.88,176.224 h1.52
  text "FR-4 High Tg" at 283.75,176.224 h1.52
  text "5.00mil" at 305.588,176.224 h1.52
  text "4.2" at 322.094,176.224 h1.52
  text "4" at 249.469,173.176 h1.52
  text "Bottom Layer" at 259.88,173.176 h1.52
  text "1.40mil" at 305.588,173.176 h1.52
  text "Bottom Solder" at 259.88,170.128 h1.52
  text "Solder Resist" at 283.75,170.128 h1.52
  text "0.40mil" at 305.588,170.128 h1.52
  text "3.5" at 322.094,170.128 h1.52
  text "Bottom Overlay" at 259.88,167.08 h1.52
  text ".Layer_Name" at 14.656,-21.222 h1.52
M13 Component Bodies Top:
  text ".Layer_Name" at 14.656,-21.222 h1.52
M14 Component Bodies Bottom:
  text ".Layer_Name" at 14.656,-21.222 h1.52
M15 Courtyards Top:
  text ".Layer_Name" at 14.656,-21.222 h1.52
M16 Courtyards Bottom:
  text ".Layer_Name" at 14.656,-21.222 h1.52
Drill Drawing:
  circle w0.254: c101.697,21.141 r0.702
  lines w0.254: 100.995,10.966 102.399,10.966 102.399,12.369 100.995,12.369 100.995,10.966 ; 100.995,14.123 101.697,14.474 102.399,14.123 102.048,14.825 102.399,15.527 101.697,15.176 100.995,15.527 101.346,14.825 100.995,14.123 ; 100.995,17.632 101.346,17.632 101.697,17.281 102.048,17.632 102.399,17.632 102.048,17.983 102.399,18.334 102.048,18.334 101.697,18.685 101.346,18.334 100.995,18.334 101.346,17.983 100.995,17.632 ; 100.995,23.597 100.995,23.947 101.346,24.298 100.995,24.649 100.995,25 101.346,25 101.697,24.649 102.048,25 102.399,25 102.399,24.649 102.048,24.298 102.399,23.947 102.399,23.597 102.048,23.597 101.697,23.947 101.346,23.597 100.995,23.597 ; 100.995,26.754 102.399,26.754 102.399,28.158 100.995,28.158 100.995,26.754 ; 100.995,30.263 101.346,30.263 101.346,29.912 102.048,29.912 102.048,30.263 102.399,30.263 102.399,30.965 102.048,30.965 102.048,31.315 101.346,31.315 101.346,30.965 100.995,30.965 100.995,30.263 ; 100.995,34.473 102.399,34.473 101.697,33.07 100.995,34.473 ; 100.995,36.578 101.346,36.578 101.697,36.227 102.048,36.578 102.399,36.578 102.048,36.929 102.399,37.28 102.048,37.28 101.697,37.631 101.346,37.28 100.995,37.28 101.346,36.929 100.995,36.578 ; 100.995,40.087 101.697,39.385 102.399,40.087 101.697,40.789 100.995,40.087 ; 100.995,43.946 102.399,43.946 101.697,42.543 100.995,43.946 ; 101.276,27.035 102.118,27.035 102.118,27.877 101.276,27.877 101.276,27.035 ; 101.276,34.192 102.118,34.192 101.697,33.35 101.276,34.192 ; 101.276,36.719 101.486,36.719 101.697,36.508 101.907,36.719 102.118,36.719 101.907,36.929 102.118,37.14 101.907,37.14 101.697,37.35 101.486,37.14 101.276,37.14 101.486,36.929 101.276,36.719
  lines w0.305: 99.723,10.018 181.807,10.018 ; 99.723,44.753 181.807,44.753 ; 108.305,6.861 108.305,47.911 ; 116.742,6.861 116.742,47.911 ; 132.91,6.861 132.91,47.911 ; 139.492,6.861 139.492,47.911 ; 149.021,6.861 149.021,47.911 ; 167.419,6.861 167.419,47.911 ; 99.723,6.861 181.807,6.861 181.807,47.911 99.723,47.911 99.723,6.861
  text "Symbol" at 101.617,45.701 h1.83
  text "Quantity" at 109.252,45.701 h1.83
  text "Finished Hole Size" at 117.689,45.701 h1.83
  text "Plated" at 133.858,45.701 h1.83
  text "Hole Type" at 140.44,45.701 h1.83
  text "Drill Layer Pair" at 149.969,45.701 h1.83
  text "Hole Tolerance" at 168.367,45.701 h1.83
  text "1" at 109.252,42.543 h1.52
  text "23.62mil (0.600mm)" at 117.689,42.543 h1.52
  text "NPTH" at 133.858,42.543 h1.52
  text "Round" at 140.44,42.543 h1.52
  text "Top Layer - Bottom Layer" at 149.969,42.543 h1.52
  text "+/-1.18mil" at 168.367,42.543 h1.52
  text "238" at 109.252,39.385 h1.52
  text "7.87mil (0.200mm)" at 117.689,39.385 h1.52
  text "PTH" at 133.858,39.385 h1.52
  text "Round" at 140.44,39.385 h1.52
  text "Top Layer - Bottom Layer" at 149.969,39.385 h1.52
  text "13" at 109.252,36.227 h1.52
  text "8.00mil (0.203mm)" at 117.689,36.227 h1.52
  text "PTH" at 133.858,36.227 h1.52
  text "Round" at 140.44,36.227 h1.52
  text "Top Layer - Bottom Layer" at 149.969,36.227 h1.52
  text "2208" at 109.252,33.07 h1.52
  text "9.84mil (0.250mm)" at 117.689,33.07 h1.52
  text "PTH" at 133.858,33.07 h1.52
  text "Round" at 140.44,33.07 h1.52
  text "Top Layer - Bottom Layer" at 149.969,33.07 h1.52
  text "13" at 109.252,29.912 h1.52
  text "40.00mil (1.016mm)" at 117.689,29.912 h1.52
  text "PTH" at 133.858,29.912 h1.52
  text "Round" at 140.44,29.912 h1.52
  text "Top Layer - Bottom Layer" at 149.969,29.912 h1.52
  text "6" at 109.252,26.754 h1.52
  text "40.95mil (1.040mm)" at 117.689,26.754 h1.52
  text "PTH" at 133.858,26.754 h1.52
  text "Round" at 140.44,26.754 h1.52
  text "Top Layer - Bottom Layer" at 149.969,26.754 h1.52
  text "2" at 109.252,23.597 h1.52
  text "157.48mil (4.000mm)" at 117.689,23.597 h1.52
  text "PTH" at 133.858,23.597 h1.52
  text "Round" at 140.44,23.597 h1.52
  text "Top Layer - Bottom Layer" at 149.969,23.597 h1.52
  text "1" at 109.252,20.439 h1.52
  text "19.69mil (0.500mm)" at 117.689,20.439 h1.52
  text "NPTH" at 133.858,20.439 h1.52
  text "Slot" at 140.44,20.439 h1.52
  text "Top Layer - Bottom Layer" at 149.969,20.439 h1.52
  text "+/-1.18mil" at 168.367,20.439 h1.52
  text "2" at 109.252,17.281 h1.52
  text "23.62mil (0.600mm)" at 117.689,17.281 h1.52
  text "PTH" at 133.858,17.281 h1.52
  text "Slot" at 140.44,17.281 h1.52
  text "Top Layer - Bottom Layer" at 149.969,17.281 h1.52
  text "+/-1.97mil" at 168.367,17.281 h1.52
  text "2" at 109.252,14.123 h1.52
  text "27.56mil (0.700mm)" at 117.689,14.123 h1.52
  text "PTH" at 133.858,14.123 h1.52
  text "Slot" at 140.44,14.123 h1.52
  text "Top Layer - Bottom Layer" at 149.969,14.123 h1.52
  text "+/-1.97mil" at 168.367,14.123 h1.52
  text "2" at 109.252,10.966 h1.52
  text "27.56mil (0.700mm)" at 117.689,10.966 h1.52
  text "PTH" at 133.858,10.966 h1.52
  text "Slot" at 140.44,10.966 h1.52
  text "Top Layer - Bottom Layer" at 149.969,10.966 h1.52
  text "+/-1.97mil" at 168.367,10.966 h1.52
  text "2488 Total" at 109.252,7.808 h1.52
  text "Slot definitions :" at 101.617,5.597 h1.52
  text "Routed Path Length" at 113.066,5.597 h1.52
  text "= Calculated from tool start centre position to tool end centre position." at 126.775,5.597 h1.52
  text "Hole Length" at 113.066,4.334 h1.52
  text "= Routed Path Length + Tool Size = Slot length as defined in the PCB layout" at 121.7,4.334 h1.52
  text ".Layer_Name" at 14.656,-21.222 h1.52
M17 Embedded Cavity:
  text ".Layer_Name" at 14.656,-21.222 h1.52
M18 Embedded Assembly:
  text ".Layer_Name" at 14.656,-21.222 h1.52
M19 Embedded Keepout:
  text ".Layer_Name" at 14.656,-21.222 h1.52

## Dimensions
97.993,-0.762 to 0,0 on M2 Board Dimensions
0,-9.576 to 25.4,-9.576 on M2 Board Dimensions
0,0.584 to 30.582,43.078 on M2 Board Dimensions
